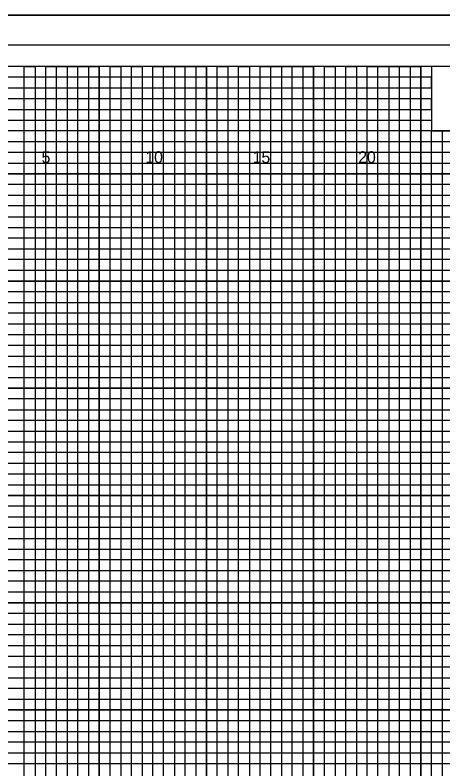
# Model space of a CAD drawing. Extents: x -4 to 103, y -2 to 209.
# Drawn here: x 54.82 to 74.78, y 32.25 to 67.4 of the extents above; entities that cross this region are included whole.
import ezdxf

# ---------------------------------------------------------------- set-up
doc = ezdxf.new("R2010")
doc.units = 0
for name, color, linetype in [('Prop XS Offset Labels', 7, 'Continuous'), ('Sheet Cross Section CELL', 7, 'Continuous'), ('Sheet Cross Section Grid Major CELL', 7, 'Continuous'), ('Sheet Cross Section Grid Middle CELL', 7, 'Continuous'), ('Sheet Cutting Line CELL', 7, 'Continuous'), ('Sheet DOT Grid CELL', 7, 'Continuous'), ('Sheet Plot Border Inside CELL', 7, 'Continuous'), ('Sheet Plot Border Outside CELL', 7, 'Continuous')]:
    doc.layers.add(name, color=color, linetype=linetype)

msp = doc.modelspace()

# ---------------------------------------------------------------- linework, layer by layer
at = {"layer": 'Sheet Cross Section CELL'}
for points in [[(102.5, 65), (0, 65), (0, 0), (102.5, 0)], [(83.75, 65), (74.25, 65), (74.25, 62), (83.75, 62)]]:
    msp.add_lwpolyline(points, close=True, dxfattribs=at)
at = {"layer": 'Sheet Cross Section Grid Major CELL'}
for points in [[(56.25, 0), (56.25, 65), (58.75, 65), (58.75, 0)], [(61.25, 0), (61.25, 65), (63.75, 65), (63.75, 0)], [(66.25, 0), (66.25, 65), (68.75, 65), (68.75, 0)], [(71.25, 0), (71.25, 65), (73.75, 65), (73.75, 0)], [(0, 62.5), (74.25, 62.5)], [(0, 57.5), (102.5, 57.5), (102.5, 60), (0, 60)], [(0, 52.5), (102.5, 52.5), (102.5, 55), (0, 55)], [(0, 47.5), (102.5, 47.5), (102.5, 50), (0, 50)], [(0, 42.5), (102.5, 42.5), (102.5, 45), (0, 45)], [(0, 37.5), (102.5, 37.5), (102.5, 40), (0, 40)], [(0, 32.5), (102.5, 32.5), (102.5, 35), (0, 35)]]:
    msp.add_lwpolyline(points, dxfattribs=at)
at = {"layer": 'Sheet Cross Section Grid Middle CELL'}
for points in [[(55.25, 0), (55.25, 65), (55.75, 65), (55.75, 0)], [(56.75, 0), (56.75, 65), (57.25, 65), (57.25, 0)], [(57.75, 0), (57.75, 65), (58.25, 65), (58.25, 0)], [(59.25, 0), (59.25, 65), (59.75, 65), (59.75, 0)], [(60.25, 0), (60.25, 65), (60.75, 65), (60.75, 0)], [(61.75, 0), (61.75, 65), (62.25, 65), (62.25, 0)], [(62.75, 0), (62.75, 65), (63.25, 65), (63.25, 0)], [(64.25, 0), (64.25, 65), (64.75, 65), (64.75, 0)], [(65.25, 0), (65.25, 65), (65.75, 65), (65.75, 0)], [(66.75, 0), (66.75, 65), (67.25, 65), (67.25, 0)], [(67.75, 0), (67.75, 65), (68.25, 65), (68.25, 0)], [(69.25, 0), (69.25, 65)], [(69.25, 65), (69.75, 65), (69.75, 0)], [(70.25, 0), (70.25, 65), (70.75, 65), (70.75, 0)], [(71.75, 0), (71.75, 65), (72.25, 65), (72.25, 0)], [(72.75, 0), (72.75, 65), (73.25, 65), (73.25, 0)], [(0, 62), (0, 63), (74.25, 63), (74.25, 63.5), (0, 63.5), (0, 64), (74.25, 64), (74.25, 64.5), (0, 64.5)], [(0, 61.5), (102.5, 61.5), (102.5, 62), (0, 62)], [(74.25, 0), (74.25, 62), (74.75, 62), (74.75, 0)], [(0, 60.5), (102.5, 60.5), (102.5, 61), (0, 61)], [(0, 59), (102.5, 59), (102.5, 59.5), (0, 59.5)], [(0, 58), (102.5, 58), (102.5, 58.5), (0, 58.5)], [(0, 56.5), (102.5, 56.5), (102.5, 57), (0, 57)], [(0, 55.5), (102.5, 55.5), (102.5, 56), (0, 56)], [(0, 54), (102.5, 54), (102.5, 54.5), (0, 54.5)], [(0, 53), (102.5, 53), (102.5, 53.5), (0, 53.5)], [(0, 51.5), (102.5, 51.5), (102.5, 52), (0, 52)], [(0, 50.5), (102.5, 50.5), (102.5, 51), (0, 51)], [(0, 49), (102.5, 49), (102.5, 49.5), (0, 49.5)], [(0, 48), (102.5, 48), (102.5, 48.5), (0, 48.5)], [(0, 46.5), (102.5, 46.5), (102.5, 47), (0, 47)], [(0, 45.5), (102.5, 45.5), (102.5, 46), (0, 46)], [(0, 44), (102.5, 44), (102.5, 44.5), (0, 44.5)], [(0, 43), (102.5, 43), (102.5, 43.5), (0, 43.5)], [(0, 41.5), (102.5, 41.5), (102.5, 42), (0, 42)], [(0, 40.5), (102.5, 40.5), (102.5, 41), (0, 41)], [(0, 39), (102.5, 39), (102.5, 39.5), (0, 39.5)], [(0, 38), (102.5, 38), (102.5, 38.5), (0, 38.5)], [(0, 36.5), (102.5, 36.5), (102.5, 37), (0, 37)], [(0, 35.5), (102.5, 35.5), (102.5, 36), (0, 36)], [(0, 34), (102.5, 34), (102.5, 34.5), (0, 34.5)], [(0, 33), (102.5, 33), (102.5, 33.5), (0, 33.5)]]:
    msp.add_lwpolyline(points, dxfattribs=at)
at = {"layer": 'Sheet Cutting Line CELL'}
msp.add_line((-3.5, 67.4), (103.4, 67.4), dxfattribs=at)
at = {"layer": 'Sheet DOT Grid CELL'}
for p, q in [((56.25, 0), (56.25, 65)), ((58.75, 0), (58.75, 65)), ((61.25, 0), (61.25, 65)), ((63.75, 0), (63.75, 65)), ((66.25, 0), (66.25, 65)), ((68.75, 0), (68.75, 65)), ((71.25, 0), (71.25, 65)), ((73.75, 0), (73.75, 65)), ((0, 62.5), (74.25, 62.5)), ((0, 60), (102.5, 60)), ((0, 57.5), (102.5, 57.5)), ((0, 55), (102.5, 55)), ((0, 52.5), (102.5, 52.5)), ((0, 50), (102.5, 50)), ((0, 47.5), (102.5, 47.5)), ((0, 45), (102.5, 45)), ((0, 42.5), (102.5, 42.5)), ((0, 40), (102.5, 40)), ((0, 37.5), (102.5, 37.5)), ((0, 35), (102.5, 35)), ((0, 32.5), (102.5, 32.5))]:
    msp.add_line(p, q, dxfattribs=at)
at = {"layer": 'Sheet Plot Border Inside CELL'}
msp.add_lwpolyline([(103, 66), (-2.8, 66), (-2.8, -1), (103, -1)], close=True, dxfattribs=at)
at = {"layer": 'Sheet Plot Border Outside CELL'}
msp.add_lwpolyline([(103.4, 67.4), (-3.5, 67.4), (-3.5, -2.425), (103.4, -2.425)], close=True, dxfattribs=at)

# ---------------------------------------------------------------- texts
at = {"layer": 'Prop XS Offset Labels'}
for s, p in [('5', (56.05742, 60.5)), ('10', (60.89708, 60.5)), ('15', (65.90575, 60.5)), ('20', (70.83125, 60.5))]:
    msp.add_text(s, height=0.55, dxfattribs=at).set_placement(p)

doc.saveas('drawing.dxf')
